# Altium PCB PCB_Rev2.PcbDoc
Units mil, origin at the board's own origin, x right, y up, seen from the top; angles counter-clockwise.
Board outline 1472.44 x 1252.14 mil, 4 copper layers (Top Layer, Layer 1 (GND), Layer 2 (PWR), Bottom Layer), stack 61.2 mil thick; 59 components, 40 nets, 212 pads, 64 vias.
Unrouted connection lines stored in the file: 48.
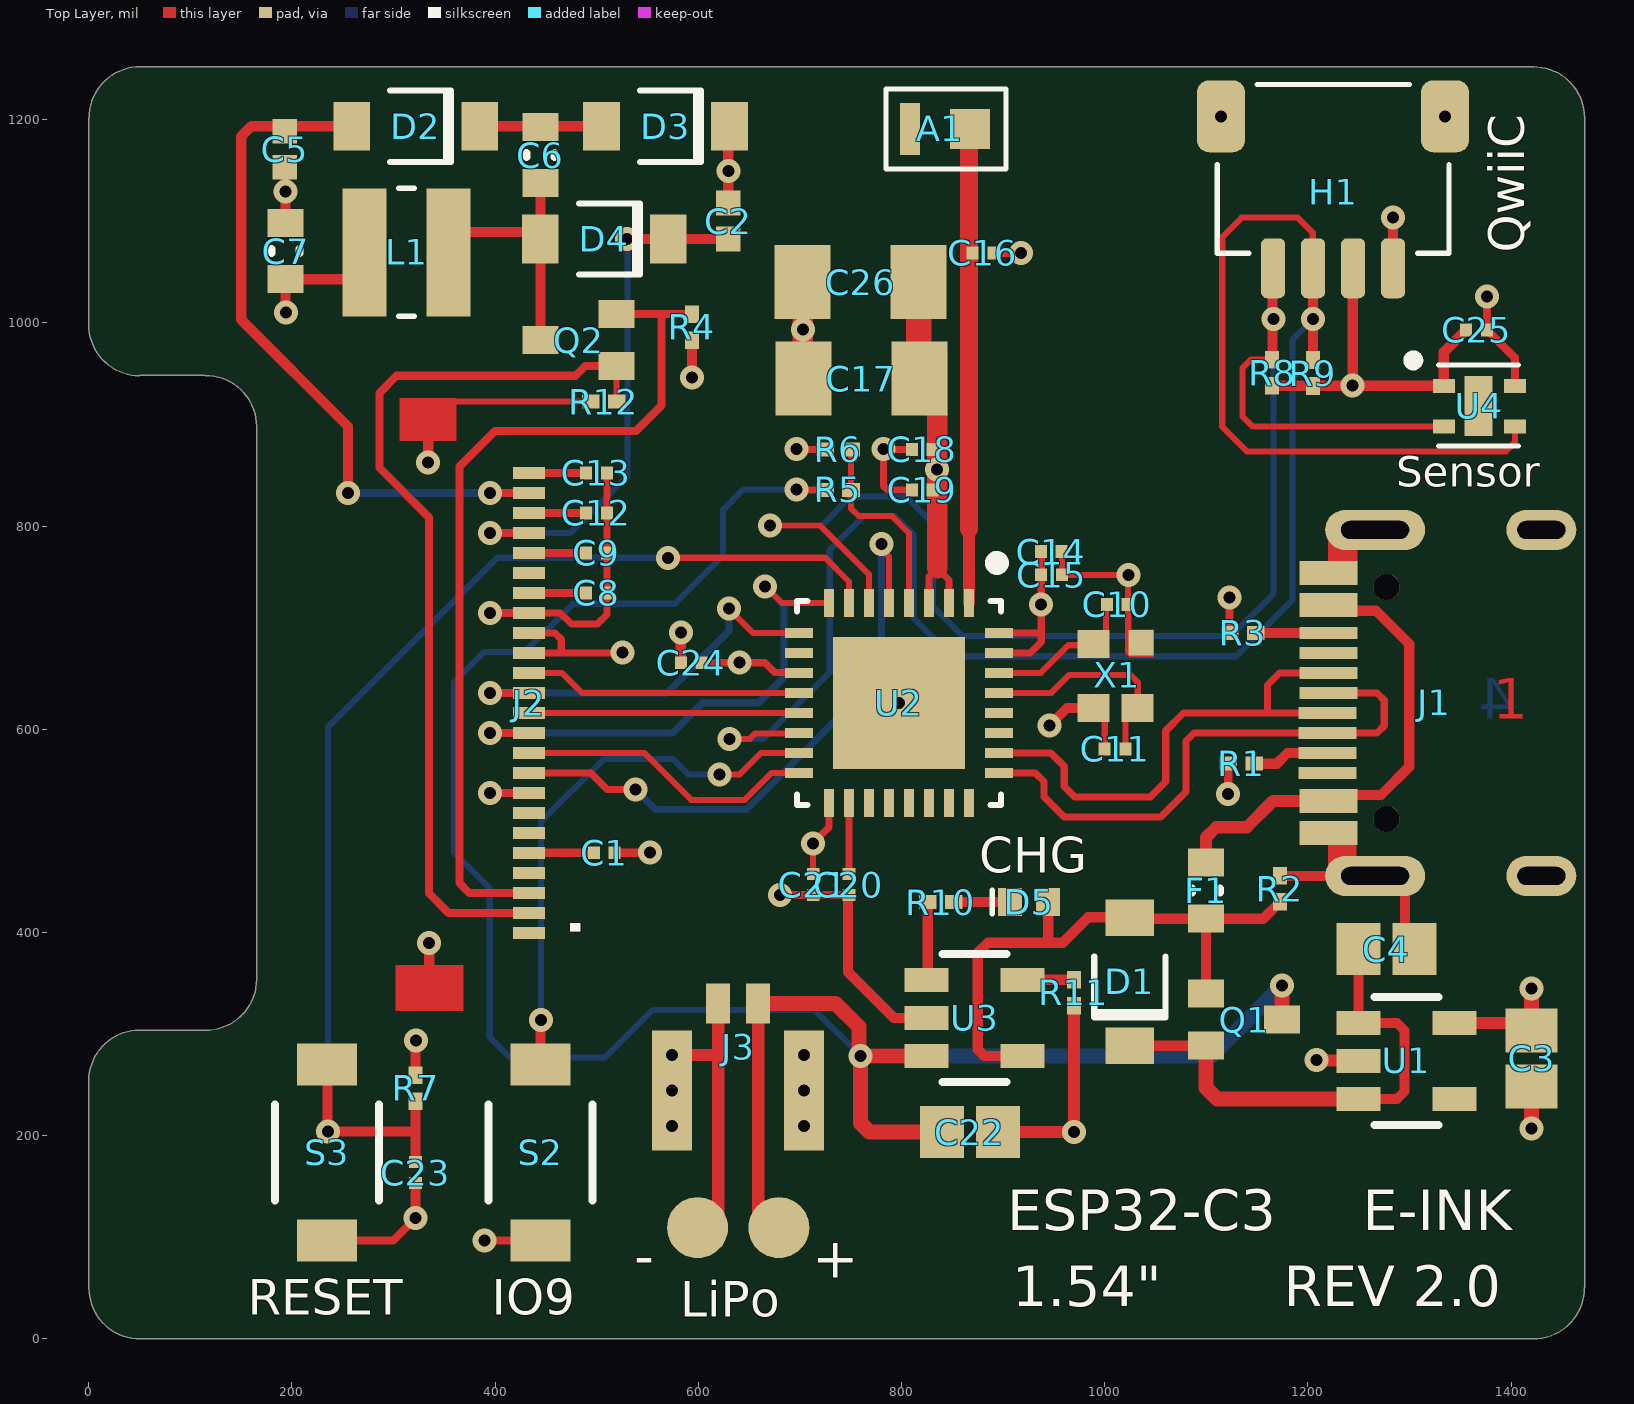
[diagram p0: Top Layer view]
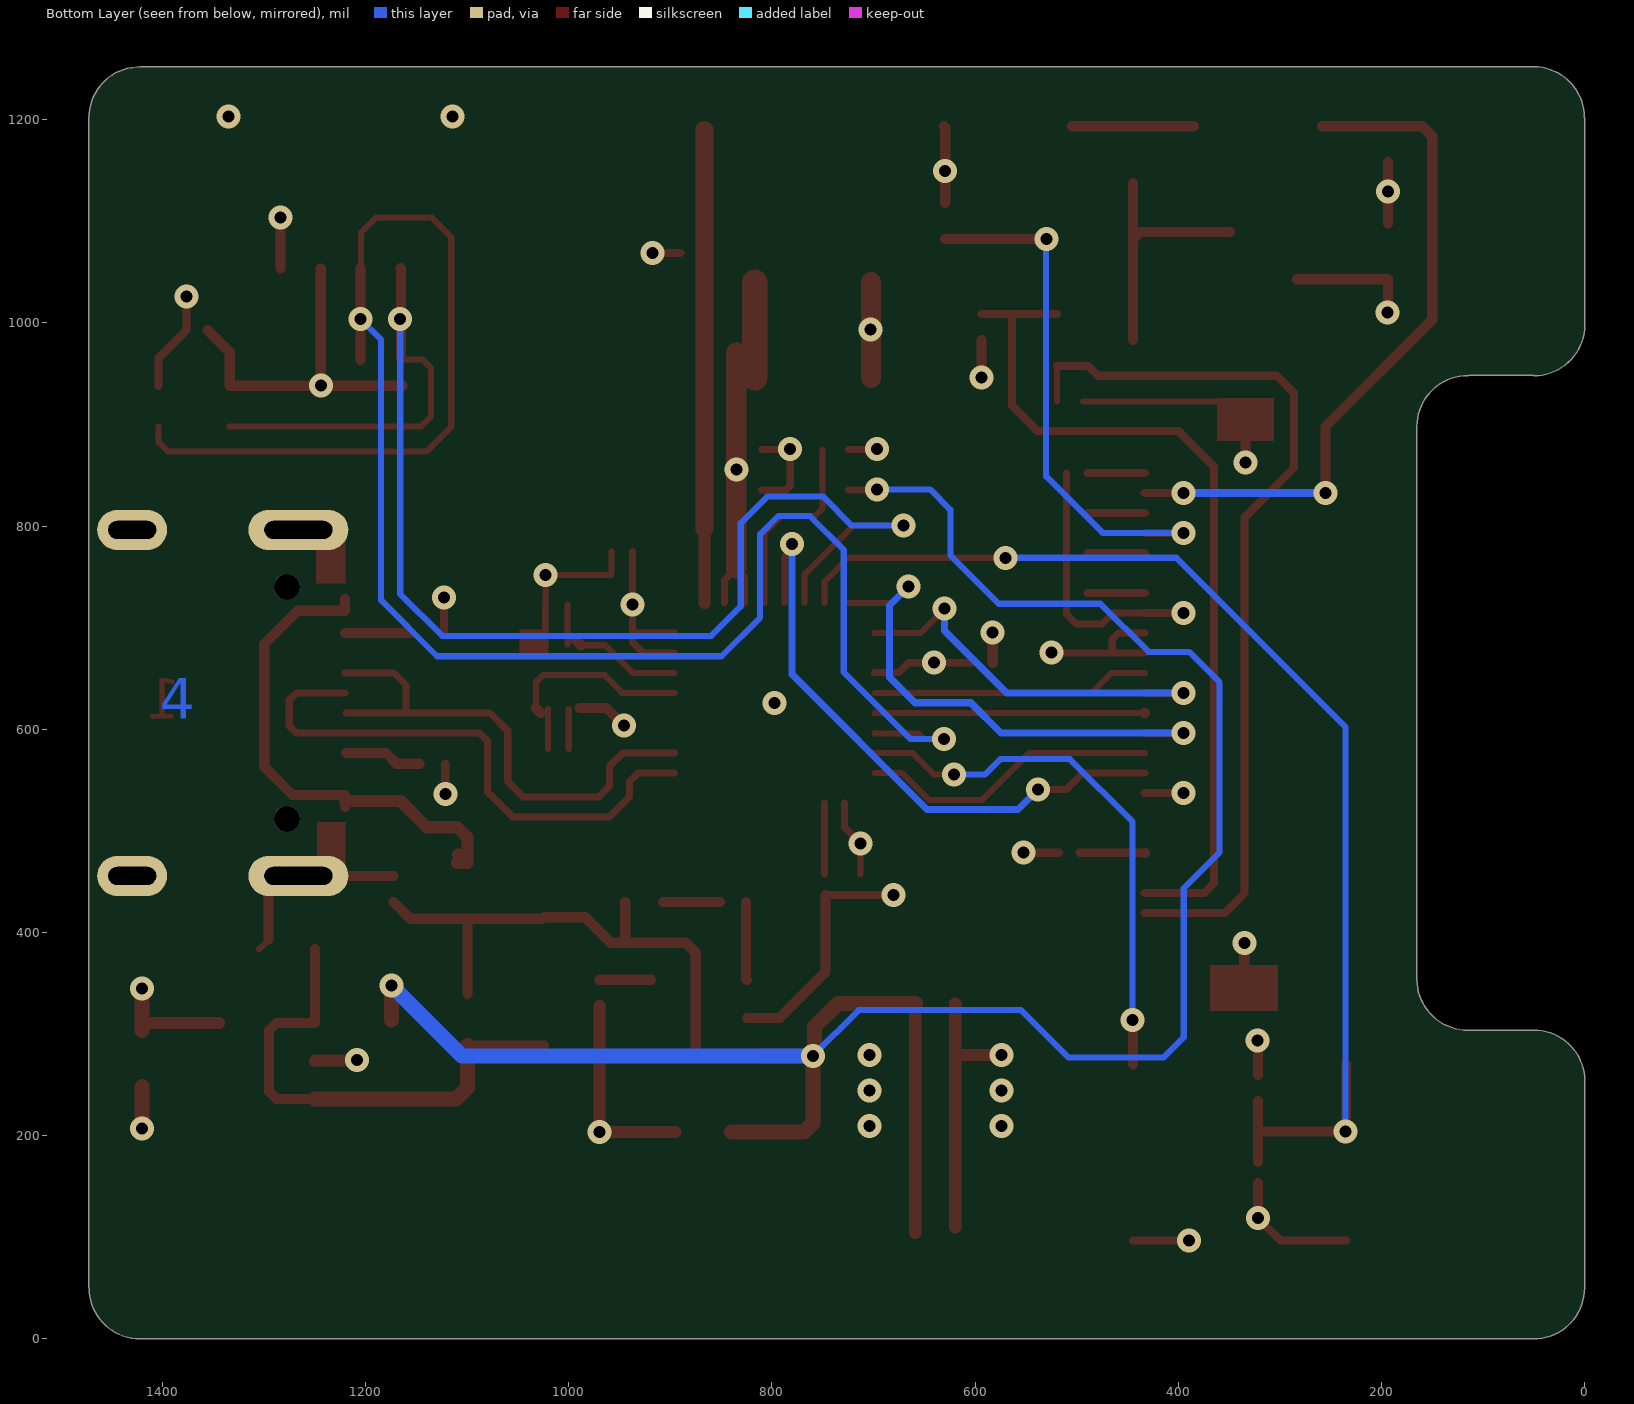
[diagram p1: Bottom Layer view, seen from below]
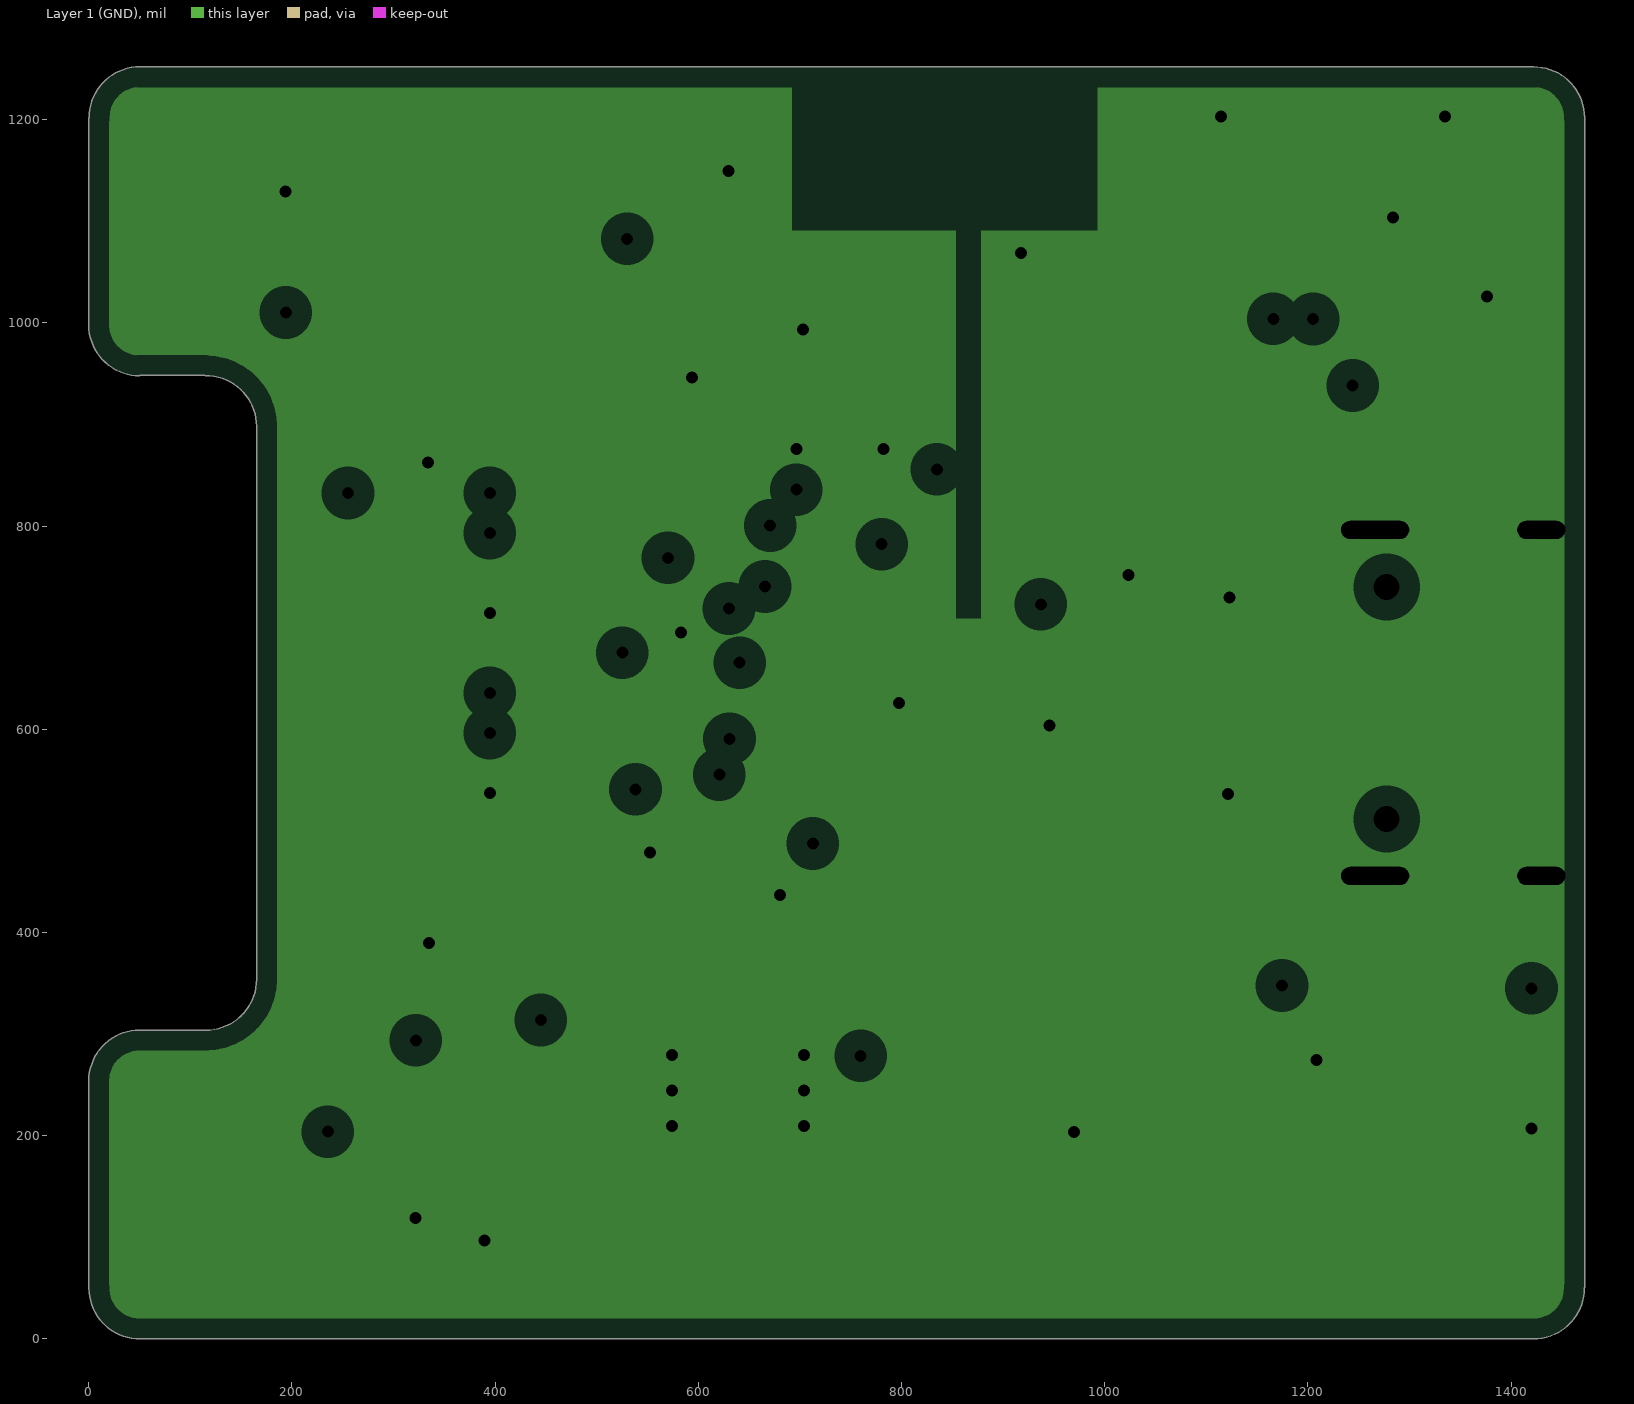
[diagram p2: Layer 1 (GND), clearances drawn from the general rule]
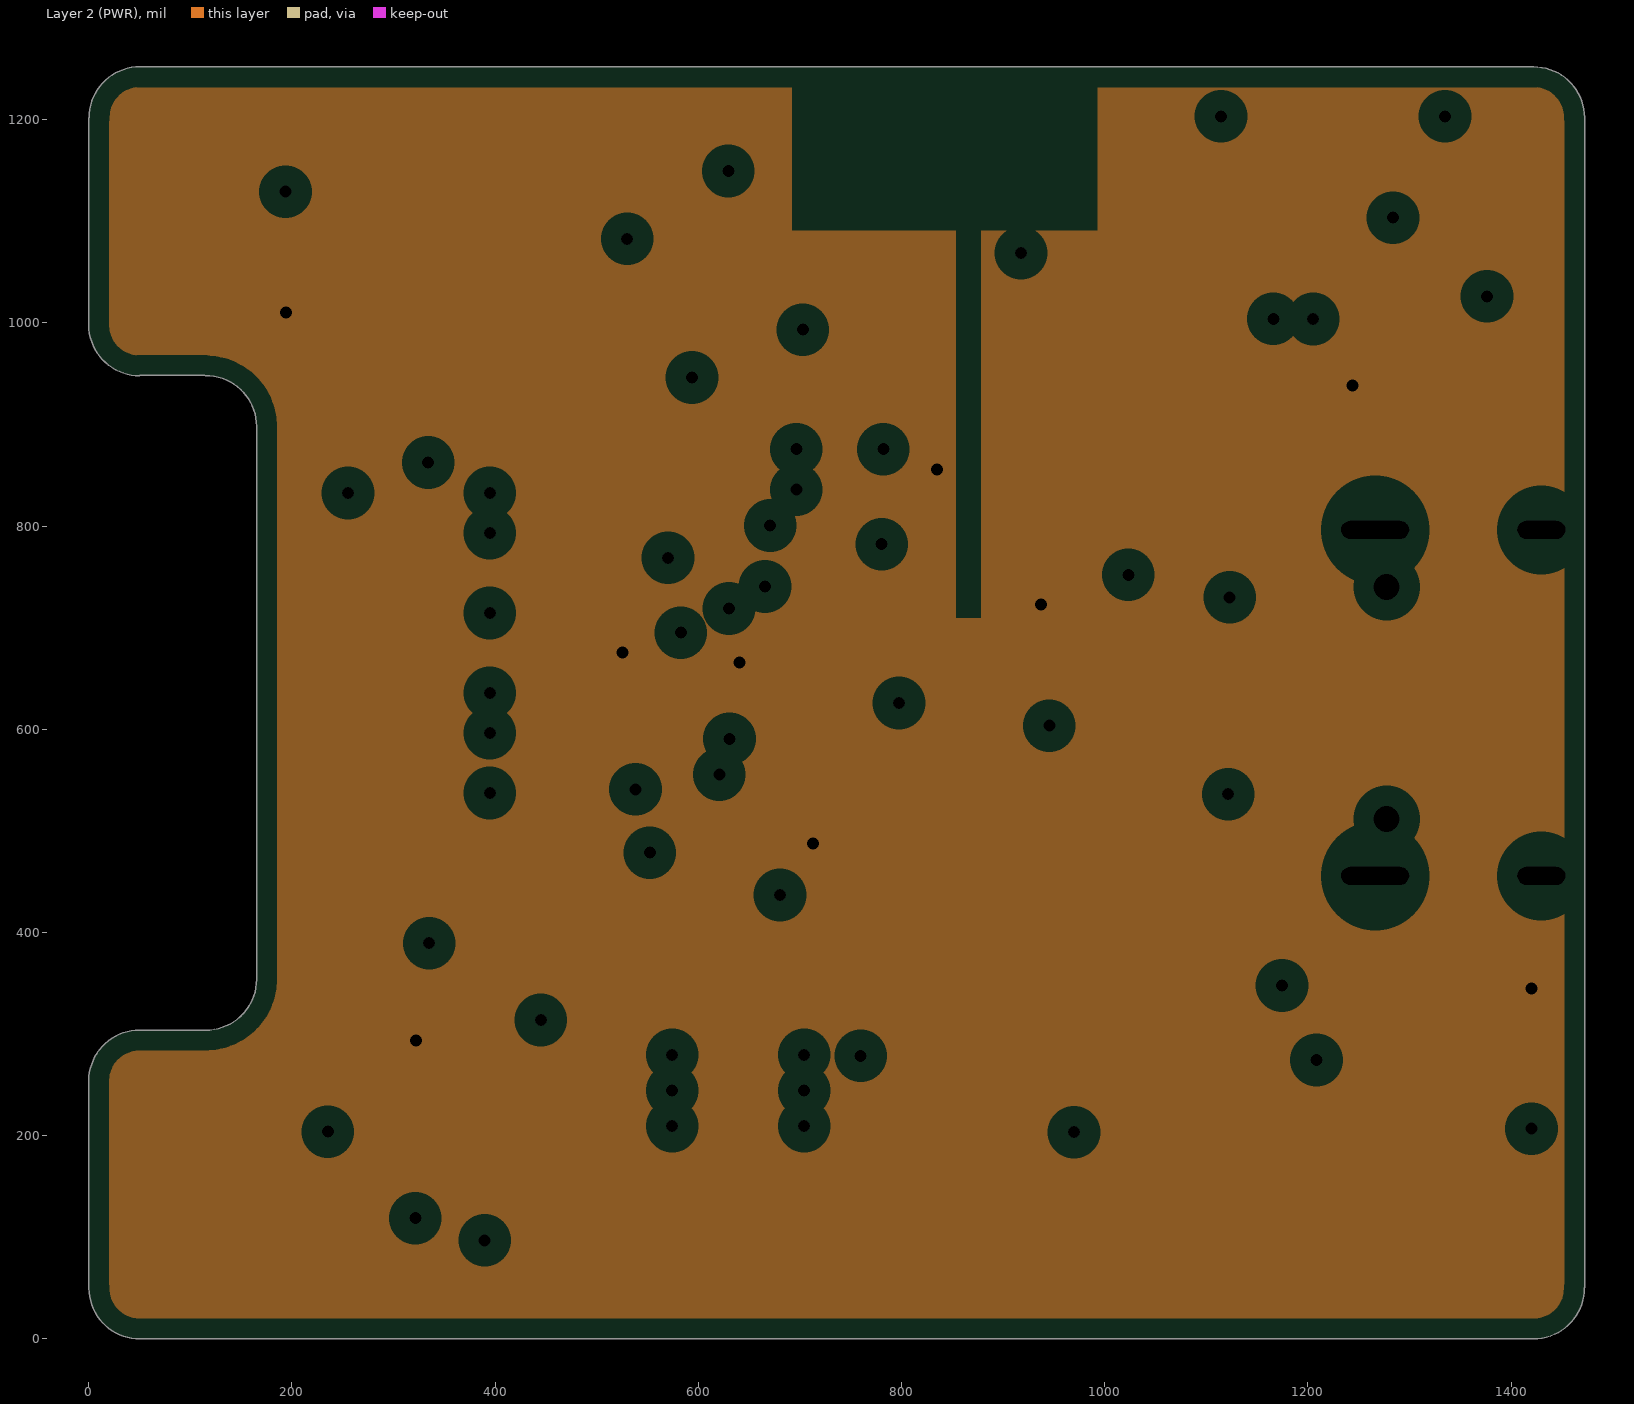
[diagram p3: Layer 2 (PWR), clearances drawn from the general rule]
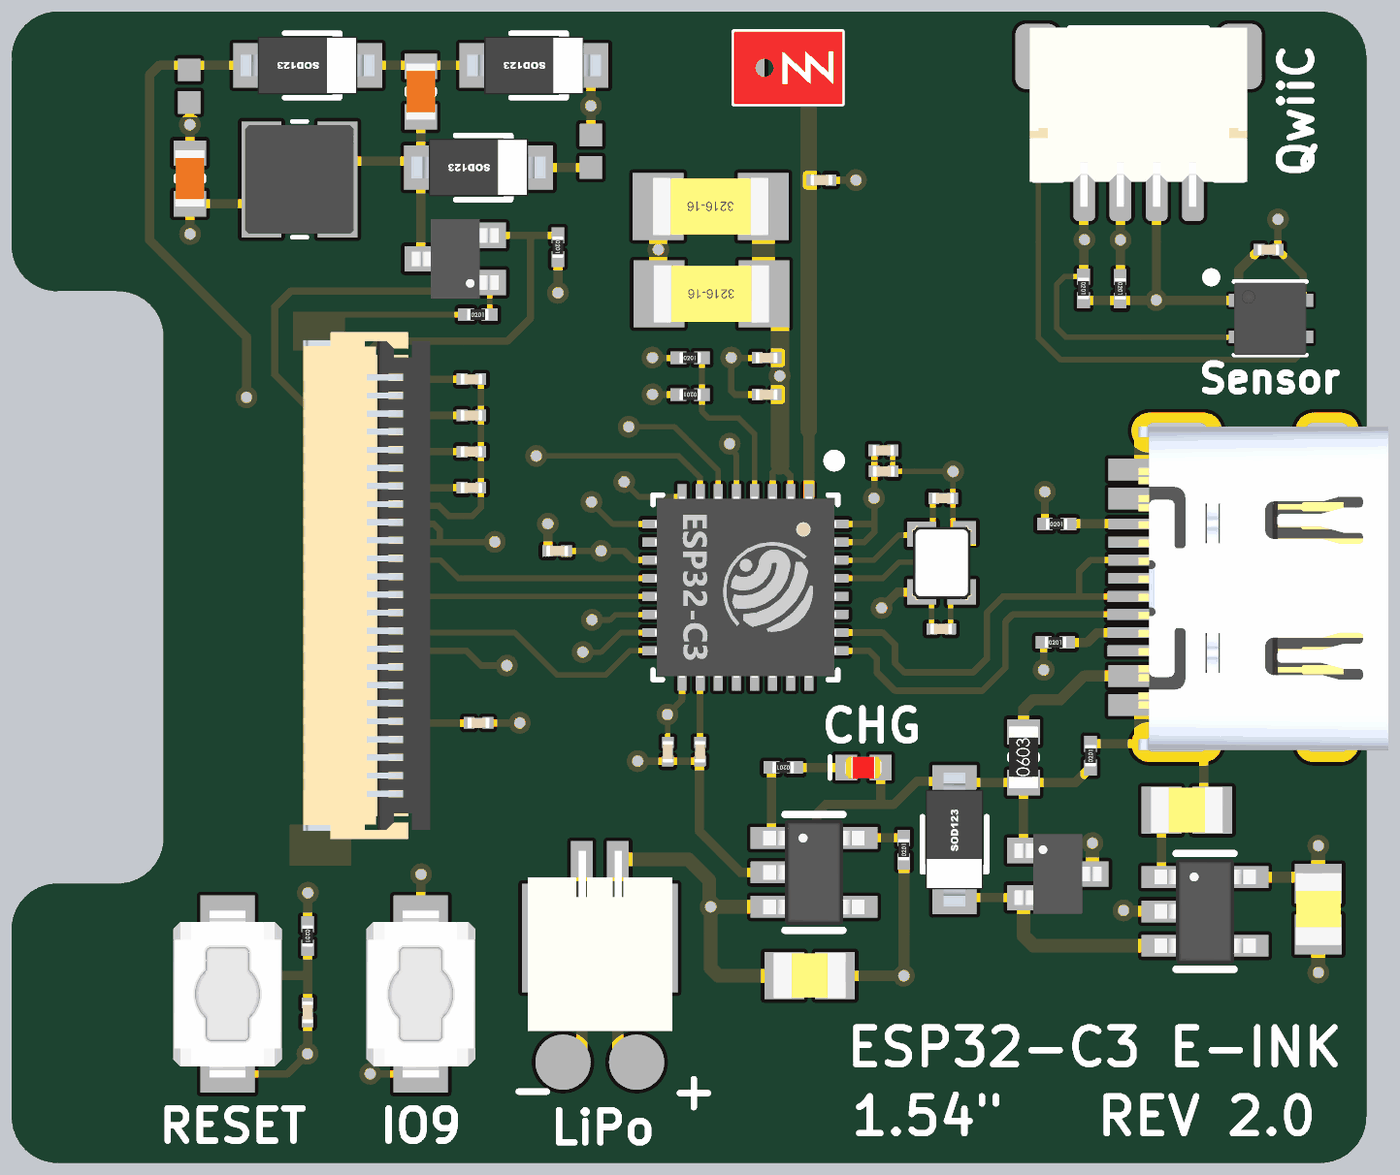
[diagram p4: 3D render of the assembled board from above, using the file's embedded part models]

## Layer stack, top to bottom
Top Solder: solder mask 0.4, Solder Resist, Dk 3.5
Top Layer: signal copper 1.4
Dielectric 2: prepreg 2.8, PP-006, Dk 4.1
Layer 1 (GND): plane copper 1.2, net GND
Dielectric 1: dielectric 50.4, FR-4, Dk 4.8
Layer 2 (PWR): plane copper 1.2, net +3.3V
Dielectric 3: prepreg 2.8, PP-006, Dk 4.1
Bottom Layer: signal copper 1.4
Bottom Solder: solder mask 0.4, Solder Resist, Dk 3.5

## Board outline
0,50 0,253.98 cw(c50,253.9) 50.11,303.9 115.11,303.9 ccw(c115.22,353.9) 165.22,353.82 165.22,898.14 ccw(c115.22,898.06) 115.11,948.06 113.94,948.28 50.11,948.28 50.11,948.06 cw(c50,998.06) 0,997.98 0,1202.03 0.29,1202.03 cw(c50.29,1202.14) 50.22,1252.14 50.22,1251.97 1422.11,1251.97 1422.11,1252.06 cw(c1422.22,1202.06) 1472.22,1202.14 1472.44,1202.14 1472.44,50.25 1472.14,50.25 cw(c1422.14,50.14) 1422.22,0.14 1422.22,0 50.32,0 50.32,0.08 cw(c50.22,50.08)

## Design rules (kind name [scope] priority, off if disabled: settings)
Clearance Clearance_CAP [All vs HasFootprint('CAPC0603X56N')] p1: gap=8.5 ignorepadtopadclearanceinfootprint=FALSE
Clearance Clearance_RES [All vs (HasFootprint('RESC0603X40L (0201 footprint)'))] p2: gap=8.2 ignorepadtopadclearanceinfootprint=FALSE
Clearance Clearance_U4 [All vs InComponent('U4')] p3: gap=5 ignorepadtopadclearanceinfootprint=FALSE
Clearance Clearance_J1 [All vs InComponent('J1')] p4: gap=5 ignorepadtopadclearanceinfootprint=FALSE
Clearance Clearance_J2 [All vs InComponent('J2')] p5: gap=5 ignorepadtopadclearanceinfootprint=FALSE
Clearance Clearance_U2 [All vs InComponent('U2')] p6: gap=5 ignorepadtopadclearanceinfootprint=FALSE
Clearance [All] p7: gap=10 ignorepadtopadclearanceinfootprint=FALSE except(0: Arc-Hole Track-Hole SMDPad-Hole THPad-Hole Via-Hole Fill-Hole Poly-Hole Region-Hole Text-Hole)
MinimumSolderMaskSliver [All] p1: minsoldermaskwidth=0.25
PlaneClearance [All] p1: clearance=20
PlaneConnect PlaneConnect_Via [(IsVia)] p1: planeconnectstyle=Direct reliefexpansion=20 reliefentries=4 reliefconductorwidth=10 reliefairgap=10
PlaneConnect [All] p2: planeconnectstyle=Relief reliefexpansion=20 reliefentries=4 reliefconductorwidth=10 reliefairgap=10
PolygonConnect [All] p1: connectstyle=Relief reliefconductorwidth=10 reliefentries=4 polygonreliefangle="90 Angle" airgapwidth=10
RoutingVias [All] p1: holewidth=28 width=50 viastyle="Through Hole" minholewidth=28 minwidth=50 maxholewidth=28 maxwidth=50
SilkToSilkClearance [All] p1: silktosilkclearance=2
SilkToSolderMaskClearance [IsPad] p1: minsilkscreentomaskgap=2 clearancetoexposedcopper=TRUE
SolderMaskExpansion [All] p1: expansion=4 istentingtop=FALSE
Width [All] p1: maxlimit=30 minlimit=6 preferedwidth=6
25 further rules are at their usual default settings.

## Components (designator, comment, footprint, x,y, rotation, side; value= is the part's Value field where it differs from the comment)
A1 "NN02-101" NN02-101 837.91,1190.98 r180 top value="Chip Antenna"
C1 "1uF" CAPC0603X56N 507.4,478.58 r180 top
C2 "1uF" CAPC1005X56N 629.49,1100.28 r90 top
C3 "10uF" CAPC2012X140N 1420.08,276.02 r270 top
C4 "10uF" CAPC2012X140N 1277.24,383.58 r0 top
C5 "1uF" CAPC1005X56N 193,1171 r90 top
C6 "4.7uF" CAPC1608X09L 444.49,1165.12 r270 top
C7 "4.7uF" CAPC1608X09L 193.69,1070.59 r90 top
C8 "1uF" CAPC0603X56N 499.69,734.25 r180 top
C9 "1uF" CAPC0603X56N 499.69,773.62 r180 top
C10 "10pF" CAPC0603X56N 1012.37,722.98 r180 top
C11 "10pF" CAPC0603X56N 1010.2,580.71 r0 top
C12 "1uF" CAPC0603X56N 499.69,812.99 r180 top
C13 "1uF" CAPC0603X56N 499.69,852.36 r180 top
C14 "1uF" CAPC0603X56N 947.37,774.98 r0 top
C15 "0.1uF" CAPC0603X56N 947.68,752.14 r0 top
C16 "1pF" CAPC0603X56N 880.08,1068.88 r0 top
C17 "100uF" CAPC3216X160N 760.52,945.17 r180 top
C18 "1uF" CAPC0603X56N 820.45,875.57 r0 top
C19 "0.1uF" CAPC0603X56N 820.45,835.57 r180 top
C20 "1uF" CAPC0603X56N 748.15,447.2 r270 top
C21 "0.1uF" CAPC0603X56N 713.15,447.2 r270 top
C22 "10uF" CAPC2012X140N 867.24,203.58 r0 top
C23 "1uF" CAPC0603X56N 321.73,163.8 r270 top
C24 "0.1uF" CAPC0603X56N 592.93,665.58 r180 top
C25 "0.1uF" CAPC0603X56N 1365.97,993.15 r0 top
C26 "100uF" CAPC3216X160N 759.69,1040.17 r180 top
D1 "MBR0520" SOD123 1024.69,351.58 r90 top
D2 "MBR0520-TP" SOD123 321.69,1193.58 r180 top value=MBR0520
D3 "MBR0520-TP" SOD123 567.69,1193.58 r180 top value=MBR0520
D4 "MBR0520-TP" SOD123 507.49,1082.56 r180 top value=MBR0520
D5 "Red Led" LED1005X40N-Red 925.67,430 r0 top
F1 "PTC" "RESC1608X06L (0603 FOOTPRINT)" 1099.69,441.14 r90 top
H1 "QWiiC" SM04B-SRSS-TB 1224.69,1128.58 r180 top locked
J1 "USB-C" TYPE-C-31-M-12 1421.81,796.26 r90 top locked
J2 "24POS Flex Connector" 687124182122 433.07,625.98 r90 top
J3 "CON2" JST_Micro_2PIN 639.21,330.2 r0 top
L1 "68uH" "INDUCTOR, 3mmX3mm" 312.87,1069.57 r180 top
Q1 "LP1480WT1G" SC-70 1137.09,314.17 r0 top
Q2 "AO7400" SC-70 482.09,983.15 r180 top
R1 "5.1K" "RESC0603X40L (0201 footprint)" 1134.33,566.18 r0 top
R2 "100K" "RESC0603X40L (0201 footprint)" 1172.44,442.91 r90 top
R3 "5.1K" "RESC0603X40L (0201 footprint)" 1135.67,694.88 r0 top
R4 "2.2R" "RESC0603X40L (0201 footprint)" 593.69,995.94 r270 top
R5 "100K" "RESC0603X40L (0201 footprint)" 737.39,835.58 r180 top
R6 "100K" "RESC0603X40L (0201 footprint)" 737.39,875.58 r0 top
R7 "10K" "RESC0603X40L (0201 footprint)" 321.73,246.83 r270 top
R8 "10K" "RESC0603X40L (0201 footprint)" 1164.84,951.08 r270 top
R9 "10K" "RESC0603X40L (0201 footprint)" 1204.84,950.67 r270 top
R10 "4.7K" "RESC0603X40L (0201 footprint)" 838.5,430 r180 top
R11 "4K" "RESC0603X40L (0201 footprint)" 969.59,340.69 r90 top
R12 "10K" "RESC0603X40L (0201 footprint)" 506.69,922.56 r0 top
S2 "=Value" TS-1088R-02526 444.69,183.58 r270 top
S3 "=Value" TS-1088R-02526 234.69,183.58 r270 top
U1 "HT7833" SOT95P280X144-5N 1296.93,273.58 r0 top
U2 "ESP32-C3" "VFQFN-32 -ESP32-C3" 797.44,625.98 r270 top locked
U3 "MCP73831T-2ACI/OT" SOT95P280X144-5N 871.93,315.98 r0 top value=MCP73831T-2ACI
U4 "SHTC3" "DFN-4 (2.0mm X 2.0mm)" 1368.69,918.15 r0 top value=Temp/Humid
X1 "40 Mhz" OSC20X16 1012.41,653.16 r270 top

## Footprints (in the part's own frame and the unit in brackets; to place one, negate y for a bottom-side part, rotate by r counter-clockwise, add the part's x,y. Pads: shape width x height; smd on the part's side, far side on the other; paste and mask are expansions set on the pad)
687124182122 [mm] "CONN FFC TOP/BOT 24POS 0.50MM R/A"
  rect 0.3x0.8 smd: 1(-5.75,0) 2(-5.25,0) 3(-4.75,0) 4(-4.25,0) 5(-3.75,0) 6(-3.25,0) 7(-2.75,0) 8(-2.25,0) 9(-1.75,0) 10(-1.25,0) 11(-0.75,0) 12(-0.25,0) 13(0.25,0) 14(0.75,0) 15(1.25,0) 16(1.75,0) 17(2.25,0) 18(2.75,0) 19(3.25,0) 20(3.75,0) 21(4.25,0) 22(4.75,0) 23(5.25,0) 24(5.75,0)
  Top Layer region: -7.696,1.627 -6.55,1.627 -6.55,3.329 -7.696,3.329
  Top Layer region: 6.55,1.805 7.62,1.805 7.62,3.228 6.55,3.228
  body extent -6.95,-0.55 7.05,2.95, height 0.96
CAPC0603X56N [mm] "Chip Capacitor, 2-Leads, Body 0.61x0.3mm, IPC Medium Density (0201 ceramic)"
  rect 0.3x0.32 smd: 1(-0.26,0) 2(0.26,0)
  body extent -0.3,-0.15 0.3,0.15, height 0.3
CAPC1005X56N [mm] "Chip Capacitor, 2-Leads, Body 1.0x0.5mm, IPC Medium Density (0402 ceramic)"
  rect 0.62x0.62 smd: 1(-0.45,0) 2(0.45,0)
  body extent -0.55,-0.3 0.55,0.3, height 0.6
CAPC1608X09L [mm] "Chip Capacitor, 2-Leads, Body 1.6x0.8mm, IPC High Density (0603 dense)"
  rect 0.7x0.9 smd: 1(-0.7,0) 2(0.7,0)
  silkscreen extent -0.05,-0.35 0.05,0.35, body extent -0.89,-0.48 0.88,0.48, height 1.03
CAPC2012X140N [mm] "Chip Capacitor, 2-Leads, Body 2.0x1.3mm, IPC Medium Density (0805 ceramic)"
  rect 1.1x1.3 smd: 1(-0.7,0) 2(0.7,0)
  body extent -1,-0.62 1,0.63, height 1.24
CAPC3216X160N [mm] "Chip Capacitor, 2-Leads, Body 3.2x1.6mm, IPC Medium Density(C1206)"
  rect 1.4x1.85 smd: 1(-1.45,0) 2(1.45,0)
  body extent -1.6,-0.8 1.6,0.8, height 1.89
"DFN-4 (2.0mm X 2.0mm)" [mm] "DFN-4 (2.0mm X 2.0mm)"
  rect 0.55x0.35 smd mask+0.076: 1(-0.889,0.508) 2(-0.889,-0.508) 3(0.889,-0.508) 4(0.889,0.508)
  rect 0.7x1.5 smd paste-0.1 mask+0.076: 7(-0.025,0)
  silkscreen extent -1.78,-1 0.97,1.27, body extent -1.02,-1 0.98,1, height 0.75
"INDUCTOR, 3mmX3mm" [mm] "Inductor, 2-Leads, (3mmX3mm)"
  rect 1.1x3.2 smd: 1(-1.05,0) 2(1.05,0)
  silkscreen extent -0.2,-1.6 0.2,1.6, body extent -1.5,-1.5 1.5,1.5, height 1.5
JST_Micro_2PIN [mm]
  rect 0.6x1 smd: 1(0.5,0) 2(-0.5,0)
  rect 1x3 smd: ""(-1.65,-2.175) ""(1.65,-2.175)
  body extent -1.99,-4.74 2,0.24, height 2.9
LED1005X40N-Red [mm] "Chip LED 2-Leads, Body 1.0x0.5mm, (0402)"
  rect 0.6x0.7 smd: 1(-0.475,0) 2(0.475,0)
  silkscreen extent -0.92,-0.3 -0.92,0.3, body extent -0.5,-0.3 0.5,0.3, height 0.2
NN02-101 [mm] "COMPACT REACH XTEND - 101"
  rect 1x1 smd: 1(-0.75,0)
  rect 0.5x1.3 smd: 2(0.75,0)
  silkscreen extent -1.65,-1 1.35,1, body extent -1.65,-1 1.35,1, height 0.8
OSC20X16 [mm] "Crystal 2.0mm x 1.60mm 0.5mm height"
  rect 0.7x0.8 smd: 1(-0.783,-0.591) 2(0.817,-0.591) 3(0.817,0.509)
  rect 0.635x0.635 smd: 4(-0.817,0.591)
  Top Layer region: -1.138,0.196 -0.554,0.196 -0.453,0.298 -0.453,0.907 -1.138,0.907
  body extent -1.01,-0.87 1.04,0.78, height 0.4
"RESC0603X40L (0201 footprint)" [mm] "Chip Resistor, 2-Leads, Body 0.6x0.3mm, IPC Medium Density (0201)"
  rect 0.44x0.35 smd: 1(-0.325,0) 2(0.325,0)
  body extent -0.3,-0.15 0.3,0.15, height 0.21
"RESC1608X06L (0603 FOOTPRINT)" [mm] "Chip Resistor, 2-Leads, Body 1.6x0.8mm, IPC High Density (0603 dense)"
  rect 0.7x0.9 smd: 1(-0.7,0) 2(0.7,0)
  silkscreen extent -0.05,-0.35 0.05,0.35, body extent -0.85,-0.4 0.85,0.4, height 0.56
SC-70 [mm] "SOT23, 3-Leads, Body 2x1.25mm, Pitch 0.65mm"
  rect 0.9x0.7 smd: 1(-0.95,0.65) 2(-0.95,-0.65) 3(0.95,0)
  body extent -1.2,-1.1 1.2,1.1, height 1
SM04B-SRSS-TB [mm] "CONN HEADER 4POS .100 R/A QWIIC"
  rrect50% 0.6x1.5 smd: 1(1.5,1.9) 2(0.5,1.9) 3(-0.5,1.9) 4(-1.5,1.9)
  rrect50% 1.2x1.8 smd: 5(-2.8,-1.9) 5(2.8,-1.9)
  silkscreen extent -2.9,-2.69 2.9,1.52, body extent -3,-2.69 3,2.26, height 3.25
SOD123 [mil] "Molded Diode, 2-Leads, Body 2.85x1.8mm, IPC Medium Density (SOD123)"
  rect 36x48 smd: 1(-63,0) 2(63,0)
  silkscreen extent -35,-35 25,35, body extent -73,-31 73,31, height 50
SOT95P280X144-5N [mm] "SOT23, 5-Leads, Body 3.1x3.0mm (max), Pitch 0.95mm, IPC Medium Density (RFMD SOT23-5)"
  rect 1.1x0.6 smd: 1(-1.2,0.95) 2(-1.2,0) 3(-1.2,-0.95) 4(1.2,-0.95) 5(1.2,0.95)
  silkscreen extent -0.8,-1.6 0.8,1.6, body extent -1.4,-1.45 1.4,1.45, height 1.45
TS-1088R-02526 [mm] "SWITCH TACTILE SPST-NO 0.05A 12V"
  rect 1.05x1.5 smd: 1(-2.2,0) 2(2.2,0)
  silkscreen extent -1.2,-1.3 1.2,1.3, body extent -2.3,-1.5 2.3,1.5, height 2
TYPE-C-31-M-12 [mm] "USB-C Connector"
  oval 1x1.75 hole 0.45 slot 1.2 at 90 deg: 1(-8.65,-0.2) 1(0,-0.2)
  oval 1x2.5 hole 0.45 slot 1.7 at 90 deg: 1(-8.65,3.955) 1(0,3.955)
  rect 0.3x1.45 smd: A1(-7.726,5.119) A4(-6.926,5.117) A5(-5.575,5.142) A6(-4.575,5.142) A7(-4.075,5.117) A8(-3.075,5.117) A9(-1.727,5.117) A12(-0.924,5.117) B1(-1.224,5.117) B4(-2.021,5.117) B5(-2.575,5.117) B6(-3.575,5.117) B7(-5.075,5.142) B8(-6.075,5.142) B9(-6.626,5.117) B12(-7.426,5.119)
  round 0.65 hole 0.65 unplated: ""(-7.225,3.667) ""(-1.425,3.667)
  body extent -8.82,-1.89 0.12,5.01, height 3.31
"VFQFN-32 -ESP32-C3" [mm] "Quad Flat Pack 32 Pin 5x5x0.85mm"
  rect 0.7x0.25 smd: 1(-2.5,1.75) 2(-2.5,1.25) 3(-2.5,0.75) 4(-2.5,0.25) 5(-2.5,-0.25) 6(-2.5,-0.75) 7(-2.5,-1.25) 8(-2.5,-1.75) 17(2.5,-1.75) 18(2.5,-1.25) 19(2.5,-0.75) 20(2.5,-0.25) 21(2.5,0.25) 22(2.5,0.75) 23(2.5,1.25) 24(2.5,1.75)
  rect 0.25x0.7 smd: 9(-1.75,-2.5) 10(-1.25,-2.5) 11(-0.75,-2.5) 12(-0.25,-2.5) 13(0.25,-2.5) 14(0.75,-2.5) 15(1.25,-2.5) 16(1.75,-2.5) 25(1.75,2.5) 26(1.25,2.5) 27(0.75,2.5) 28(0.25,2.5) 29(-0.25,2.5) 30(-0.75,2.5) 31(-1.25,2.5) 32(-1.75,2.5)
  rect 3.3x3.3 smd paste-5 mask+0.102: 33(0,0)
  silkscreen extent -3.65,-2.55 2.55,2.6, body extent -2.5,-2.5 2.5,2.5, height 1.12

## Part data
A1: "Antenna Chip 2.4Gig", Manufacturer=Ignion
C1 C8 C9 C12 C13 C14 C18 C20 C23: library part CAP_0201, "CAP 1uF 0201"
C2 C5: library part CAP_0402, "CAP 1uF 0402"
C3 C4 C22: library part CAP_0805, "CAP 10uF 0805"
C6 C7: library part CAP_0603, "CAP 4.7uF 50V 0603"
C10 C11: library part CAP_0201, "CAP 10pF 0201"
C15 C19 C21 C24 C25: library part CAP_0201, "CAP 0.1uF 0201"
C16: library part CAP_0201, "CAP 1pF 0201"
C17 C26: library part CAP_1206, "CAP 100uF 1206"
D1: library part MBR0520-TP, "DIODE SCHOTTKY 20V 500MA SOD-123", Manufacturer=Micro
D2 D3 D4: "DIODE SCHOTTKY 20V 500MA SOD-123", Manufacturer=Micro
D5: library part LED_0402_SMALL_Red, "LED Red 0402", Manufacturer=Lite-On
F1: library part PTC_FUSE_0603, "PTC FUSE ?mA hold, ?A trip 0603"
H1: library part SM04B-SRSS-TB, "CONN HEADER 4POS .100 R/A QWIIC", Manufacturer=JST
J1: "CONN RECPT USB-C", Manufacturer=KHE
J2: library part 687124182122, "CONN FFC TOP/BOT 24POS 0.50MM R/A", Manufacturer=Wurth
J3: library part JST_Micro_CONN_2PIN, "JST MIcro CONN 2POS"
L1: "INDUCTOR 68uH 20% 4mmx4mm", Manufacturer=SXN
Q1: "MOSFET P-CH 20V 1.4A SC-70", Manufacturer=LRC
Q2: "MOSFET N-CH 20V 4A SC70-3", Manufacturer="VBSemi Elec"
R1 R3: library part RES_0201, "RES 0201 5.1K"
R2 R5 R6: library part RES_0201, "RES 100K 0201"
R4: library part RES_0201, "RES 2.2R 0201"
R7 R8 R9 R12: library part RES_0201, "RES 10K 0201"
R10: library part RES_0201, "RES 4.7K 0201"
R11: library part RES_0201, "RES 4K 0201"
S2 S3: library part TS-1088R-02526, "Tactile Micro Switch", Manufacturer=XUNPU
U1: "IC LDO 3.3V 0.5A SOT23-5", Manufacturer=Holtek
U2: "WIFI/Bluetooth, VFQFN-32", Manufacturer=Espressif
U3: "Charger IC Lithium-Ion/Polymer SOT23-5", Manufacturer=Microchip
U4: "Humidity/Temperature Sensor", Manufacturer=Sensirion
X1: library part 40Mhz, "CRYSTAL 40MHZ 10PF SMD", Manufacturer=ECS

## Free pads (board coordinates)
  round 60 smd: 2(599.21,109.57) 2(679.21,109.57)

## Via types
v1: diameter 23.62, hole 11.81, Top Layer to Bottom Layer, tented both sides, 64 vias

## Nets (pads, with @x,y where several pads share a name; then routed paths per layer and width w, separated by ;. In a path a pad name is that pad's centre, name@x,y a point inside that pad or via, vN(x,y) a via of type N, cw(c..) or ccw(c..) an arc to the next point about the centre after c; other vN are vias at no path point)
+3.3V: C3.1 C7.1 C14.1 C15.1 C17.1 C18.2 C19.1 C21.1 C24.1 C25.1 C26.1 H1.3 J2.15 J2.16 L1.2 R7.1 R8.2 R9.2 U1.5 U2.2 U2.3 U2.11 U2.17 U2.31 U2.32 U4.1 | length 1504.2
  Top Layer w6: v1(712.7,487.7) 712.92,487.47 712.92,457.67 C21.1 ; C17.1@813.36,946.41 C17.1@814.19,945.58 ; v1(1243.94,938.41) v1@1244.16,938.62 ; H1.3@1244.16,1053.57 H1.3
  Top Layer w7: J2.15 465.08,675.2 ; J2.16 458.78,694.88 465.08,688.58 465.08,675.2 ; v1@524.84,675.2 465.08,675.2 ; C24.1 v1(640.65,665.58) 665.65,665.58 675.48,655.75 698.78,655.75 U2.11@698.94,655.59 ; v1(712.7,487.7) 728.54,503.54 U2.17 ; U2.3 826.97,750.47 835.08,758.58 846.57,747.09 U2.2@846.57,724.49 ; U2.31 926.69,675.2 937.44,685.95 937.44,694.88 ; U2.32 937.44,694.88 ; C14.1@937.44,774.98 C15.1 937.44,723.29 v1(937.13,722.98) 937.44,722.68 937.44,694.88
  Top Layer w10: v1@193.69,1009.98 C7.1 L1.2@283.32,1043.03 ; R7.1 v1@321.73,293.56 ; R8.2@1163.69,938.15 1204.84,938.15 v1@1243.69,938.15 ; v1(1243.94,938.41) v1@1243.69,938.15 ; v1@1244.16,938.62 H1.3@1244.16,1053.57 ; C25.1 1333.69,971.1 U4.1 v1@1243.69,938.15 ; C3.1@1412.68,310.98 C3.1
  Top Layer w12: U1.5 C3.1@1412.68,310.98
  Top Layer w15: C3.1 v1(1420.08,345)
  Top Layer w20: 835.08,758.58 835.08,780.84 835.08,835.58 835.08,855.97 835.08,875.58 C17.1@835.08,970.58
  Top Layer w25: C17.1@816.78,946 C26.1
  other v1: 321.98,293.81 525.1,675.45 834.69,855.97 193.94,1010.23
A0: R5.1 R6.2 U2.4 | length 194
  Top Layer w6: R6.2 750.19,817.58 757.62,810.15 790.36,810.15 807.28,793.23 U2.4
D+: J1.A6 J1.B6 U2.26 | length 509.3
  Top Layer w7: U2.26 946.89,576.77 960.08,563.58 960.08,543.58 970.08,533.58 1045.08,533.58 1060.08,548.58 1060.08,598.58 1077.64,616.14 1160.08,616.14 ; J1.A6 1160.08,616.14 ; J1.B6 1172.01,655.51 1160.08,643.58 1160.08,616.14
D-: J1.A7 J1.B7 U2.25 | length 555.3
  Top Layer w7: U2.25 931.57,557.09 940.08,548.58 940.08,533.58 960.08,513.58 1055.08,513.58 1080.08,538.58 1080.08,588.58 1087.95,596.46 J1.B7 1267.95,596.46 1275.08,603.58 1275.08,628.58 1267.83,635.83 J1.A7
E-INK_BSY: J2.9 U2.5 | length 606
  Top Layer w6: v1(780.33,782.18) 780.33,777.41 787.6,770.14 U2.5
  Top Layer w7: J2.9 494.14,557.09 510.35,540.88 v1(538.1,540.88)
  Bottom Layer w7: v1(538.1,540.88) 557.8,521.18 647.28,521.18 780.33,654.23 v1(780.33,782.18)
E-INK_CS: J2.12 U2.13 | length 265.9
  Top Layer w6: J2.12 U2.13
E-INK_DC: J2.11 U2.8 | length 517.1
  Top Layer w6: v1(665.65,740.58) 681.82,724.41 U2.8
  Top Layer w8: v1(394.84,596.46) J2.11
  Bottom Layer w7: v1(394.84,596.46) 574.54,596.46 604.27,626.18 659.33,626.18 684.33,651.18 684.33,721.9 v1(665.65,740.58)
E-INK_RST: J2.10 U2.16 | length 296.1
  Top Layer w6: J2.10 546.69,576.77 592.88,530.58 645.65,530.58 672.15,557.09 U2.16
EN: C23.1 R7.2 S3.1 U2.7 | length 1223.7
  Top Layer w6: v1(570.1,768.88) 724.78,768.88 748.15,745.51 U2.7@748.15,724.49
  Top Layer w10: S3.1 235.08,269.8 v1@235.08,203.78 ; v1(235.33,204.04) 321.73,204.04 ; C23.1 321.73,204.04 ; R7.2 321.73,204.04
  Bottom Layer w6: v1(235.33,204.04) 235.33,602.18 402.03,768.88 v1(570.1,768.88)
GDR: J2.2 Q2.1 R12.2 | length 898.3
  Top Layer w6: R12.2 Q2.1
  Top Layer w8: J2.2 354.17,419.29 334.84,438.62 334.84,808.62 286,857.46 286,931 303,948 479.1,948 488.66,957.56 Q2.1
GND: C1.1 C2.2 C3.2 C4.2 C5.1 C7.2 C8.1 C9.1 C10.1 C11.1 C12.1 C13.1 C14.2 C15.2 C16.2 C17.2 C18.1 C19.2 C20.2 C21.2 C22.2 C23.2 C24.2 C25.2 C26.2 D3.1 H1.4 H1.5 J1.1 J1.A1 J1.A12 J1.B1 J1.B12 J2.8 J2.17 J3. J3.2 pad.2@599.21,109.57 R1.1 R2.2 R3.1 R4.2 R6.1 R11.1 R12.1 S2.2 S3.2 U1.2 U2.33 U3.2 U4.4 X1.2 X1.4 | length 2647.2
  Top Layer w6: 334.08,891.58 334.49,891.99 334.49,912.56 344.49,922.56 R12.1 ; C17.2@699.19,946.41 C17.2@700.02,945.58 ; C14.2 957.76,774.83 957.76,752.29 C15.2 957.99,752.06 1023.06,752.06 v1(1023.13,751.98) 1022.87,751.72 1022.87,723.25 C10.1 ; C11.1 X1.2@999.97,619.98 ; 1023.13,683.71 C10.1@1023.13,722.98 ; J1.1@1266.1,455.71 1286.6,455.71 J1.1@1295.39,446.92 ; C4.2@1295.39,392.99 C4.2
  Top Layer w7: J2.17 464.09,714.57 475.08,703.58 500.51,703.58 509.92,712.99 C13.1 ; v1@696.17,875.58 R6.1 ; v1(782.04,875.82) 782.04,839.67 786.14,835.57 C19.2 ; v1@782.29,875.57 C18.1
  Top Layer w8: S3.2 299.65,96.97 v1(321.47,118.79) ; v1(389.69,96.97) S2.2 ; v1(394.84,537.4) J2.8 ; v1(394.84,714.57) J2.17 ; C1.1 v1(552.2,478.58) ; v1(680.39,436.97) C20.2 ; C16.2 v1(917.53,1068.88) ; v1(1121.54,536.18) R1.1 ; R3.1 v1(1122.87,729.88) ; v1(1376.2,1026.18) C25.2 1403.69,965.67 U4.4
  Top Layer w10: C7.2 v1(193.69,1129.15) C5.1@193.69,1158.15 ; v1@321.73,119.04 C23.2 ; v1(334.08,862.58) 334.08,891.58 ; 335.08,360.58 v1(335.08,389.58) ; C24.2 v1(582.69,695.15) ; v1(593.69,946.26) R4.2 ; C2.2@629.69,1117.99 629.49,1118.19 629.49,1192.39 D3.1 ; C20.2@747.44,436.97 747.44,360.83 792.28,315.98 U3.2 ; v1(945.39,603.58) 962.8,620.98 X1.2 ; R2.2 J1.1@1266.1,455.71 ; H1.4 v1(1283.74,1103.58) ; C4.2@1295.39,392.99 J1.1@1295.39,446.92
  Top Layer w12: v1(574.25,279.57) 612.5,279.57 ; pad.2@619.53,109.57 J3.2 ; C22.2 v1(969.69,203.58) R11.1@969.69,327.89 ; v1(1208.39,274.58) 1208.89,274.08 1249.19,274.08 U1.2
  Top Layer w15: v1(1420.08,207.05) C3.2
  Top Layer w20: C17.2@702.6,946 C26.2
  other v1: 574.25,209.57 704.17,209.57 574.25,244.57 704.17,244.57 704.17,279.57 797.44,625.98 696.42,875.84 702.86,993.34 629.49,1149.56 1114.45,1203.39 1334.92,1203.39
GPIO2: H1.1 R8.1 U2.6 U4.2 | length 1417.9
  Top Layer w6: v1(670.65,800.58) 719.93,800.58 767.91,752.6 U2.6 ; R8.1@1165.16,963.88 R8.1 1143.84,963.88 1135.69,955.72 1135.69,907.78 1145.32,898.15 U4.2
  Top Layer w10: R8.1@1165.16,963.88 1165.16,1053.31 H1.1
  Bottom Layer w6: v1(670.65,800.58) 721.3,800.58 749.69,828.97 804.69,828.97 830.69,802.97 830.69,720.97 859.69,691.97 1124.69,691.97 1165.89,733.17 v1(1165.89,1004.04)
GPIO8: H1.2 R9.1 U2.14 U4.3 | length 1932.2
  Top Layer w6: v1(630.65,590.58) 650.65,590.58 656.08,596.02 698.58,596.02 U2.14 ; H1.2 1204.67,1054.11 1204.67,1088.79 1189.84,1103.62 1134.84,1103.62 1115.69,1084.46 1115.69,897.78 1139.84,873.62 1394.84,873.62 1403.69,882.46 U4.3
  Top Layer w10: R9.1 1204.84,1053.62 H1.2
  Bottom Layer w6: v1(630.65,590.58) 663.73,590.58 729.33,656.18 729.33,776.61 762.69,809.97 793.69,809.97 811.69,791.97 811.69,709.97 849.69,671.97 1129.69,671.97 1184.69,726.97 1184.69,983.46 v1(1205.1,1003.88)
GPIO9: S2.1 U2.15 | length 533.1
  Top Layer w6: v1(620.65,555.58) 640.65,555.58 661.83,576.77 U2.15
  Top Layer w10: S2.1 v1@444.69,313.62
  Bottom Layer w6: v1(444.94,313.88) 444.94,508.84 506.78,570.68 575.1,570.68 590.2,555.58 v1(620.65,555.58)
LiPO: C22.1 J3.1 pad.2@679.21,109.57 Q1.3 R5.2 U3.3 | length 2288
  Top Layer w7: v1@696.17,835.58 R5.2
  Top Layer w12: pad.2@658.9,104.57 J3.1
  Top Layer w15: J3.1 735.07,330.2 758.04,307.23 758.04,280.23 v1(759.69,278.58) ; U3.3@814.69,278.58 v1(759.69,278.58) ; C22.1 768.47,203.58 759.69,212.37 v1(759.69,278.58) ; Q1.3 v1(1174.49,347.83)
  Bottom Layer w6: v1@693.13,836.24 644.39,836.24 624.33,816.18 624.33,771.18 576.77,723.62 476.77,723.62 429.33,676.18 389.33,676.18 359.33,646.18 359.33,478.94 394.69,443.58 394.69,296.97 414.69,276.97 508.07,276.97 554.69,323.58 714.69,323.58 v1(759.69,278.58)
  Bottom Layer w15: v1(759.69,278.58) 1105.24,278.58 v1(1174.49,347.83)
  other v1: 696.42,835.84
MISO: U2.10
MOSI: J2.14 U2.12 | length 274.1
  Top Layer w6: J2.14 465.72,655.51 485.4,635.83 U2.12
NetA1_1: A1.1 C16.1 U2.1 | length 467
  Top Layer w10: A1.1@866.34,1189.88 A1.1
  Top Layer w12: U2.1 866.34,797.44
  Top Layer w18: 866.34,797.44 A1.1@866.34,1189.88
NetC1_2: C1.2 J2.5 | length 64.1
  Top Layer w8: J2.5@433.19,478.46 C1.2@497.17,478.46
  Top Layer w10: J2.5 J2.5@433.19,478.46
NetC4_1: C4.1 D1.1 Q1.2 U1.1 U1.3 | length 500.5
  Top Layer w10: D1.1 Q1.2 ; U1.3 1287.68,236.18 1295.08,243.58 1295.08,303.58 1287.68,310.98 U1.1 C4.1
  Top Layer w15: Q1.2 1099.69,247.2 1110.71,236.18 U1.3
NetC6_1: C6.1 D2.1 D3.2 | length 120
  Top Layer w10: D2.1 444.69,1193.58 D3.2
NetC6_2: C6.2 D4.2 L1.1 Q2.3 | length 252.6
  Top Layer w10: L1.1@349.19,1089.57 437.48,1089.57 441.79,1085.26 D4.2 ; Q2.3 444.69,1082.56 444.69,1088.15 C6.2@444.69,1137.56
NetC8_2: C8.2 J2.18 | length 56.4
  Top Layer w8: J2.18 C8.2
NetC9_2: C9.2 J2.20 | length 56.4
  Top Layer w8: J2.20 C9.2
NetC10_2: C10.2 U2.30 X1.1 | length 152.7
  Top Layer w6: U2.30 937.01,655.51 964.24,682.75 X1.1@987.9,682.75 ; X1.1@1001.13,683.71 C10.2@1001.13,722.98
  Top Layer w10: X1.1@987.9,682.75 X1.1 X1.1@995.08,689.93
NetC11_2: C11.2 U2.29 X1.3 | length 218.6
  Top Layer w6: U2.29 947.32,635.83 965.08,653.58 1025.08,653.58 1032.44,646.22 X1.3 ; C11.2 X1.3@1020.44,619.98
  Top Layer w10: X1.3@1027.44,615.98 X1.3
NetC12_2: C12.2 J2.22 | length 56.4
  Top Layer w8: J2.22 C12.2
NetC13_2: C13.2 J2.24 | length 56.4
  Top Layer w8: J2.24 C13.2
NetC20_1: C20.1 U2.18 | length 70
  Top Layer w7: C20.1 U2.18@748.15,527.48
NetD5_1: D5.1 R10.1 | length 55.7
  Top Layer w10: R10.1 D5.1
NetF1_2: F1.2 J1.A4 J1.A9 J1.B4 J1.B9 | length 509.5
  Top Layer w10: J1.A4 1220.36,529.48 J1.B9 1271.88,535.38 1299.69,563.19 1299.69,683.98 1266.98,716.68 J1.B4 J1.A9
  Top Layer w12: F1.2@1108.72,476.48 F1.2@1100.94,468.7 ; F1.2@1109.8,468.7 F1.2@1100.94,468.7 ; J1.B9@1220.36,529.48 1165.59,529.48 1139.69,503.58 1109.69,503.58 1099.69,493.58 F1.2 F1.2@1100.94,468.7
NetJ1_A5: J1.A5 R1.2 | length 76.6
  Top Layer w10: R1.2 1169.33,566.18 1179.92,576.77 J1.A5
NetJ1_B5: J1.B5 R3.2 | length 65
  Top Layer w10: R3.2@1155.35,694.88 J1.B5
NetR10_2: R10.2 U3.1 | length 77
  Top Layer w10: U3.1 825.71,354.41 R10.2
NetR11_2: R11.2 U3.5 | length 50.6
  Top Layer w10: U3.5 919.27,353.48 R11.2 R11.2@969.69,353.58
RESE: J2.3 Q2.2 R4.1 | length 870.2
  Top Layer w8: J2.3 374.49,438.98 364.84,448.62 364.84,858.62 399.96,893.74 538.69,893.74 563.69,918.74 563.69,1008.74 ; Q2.2 563.69,1008.74 ; R4.1 563.69,1008.74
SCLK: J2.13 U2.9 | length 399.7
  Top Layer w6: v1@629.89,718.62 653.63,694.88 U2.9
  Top Layer w8: v1(394.84,635.83) J2.13
  Bottom Layer w7: v1(394.84,635.83) 568.98,635.83 630.14,696.99 v1(630.14,718.88)
VBUS: D1.2 D5.2 F1.1 Q1.1 R2.1 U3.4 | length 574.6
  Top Layer w10: U3.4 881.42,278.58 875,285 875,380 885,390 958.7,390 983.7,415 1024.27,415 D1.2 1025.69,413.58 F1.1 ; 944.37,390.63 D5.2 ; Q1.1 F1.1 ; F1.1@1099.69,413.78 F1.1 ; R2.1 1155.91,413.58 F1.1
VGH: C2.1 D4.1 J2.21 | length 535.8
  Top Layer w8: v1(394.84,793.31) J2.21
  Top Layer w10: v1@529.65,1082.56 D4.1 C2.1
  Bottom Layer w6: v1(394.84,793.31) 474.41,793.31 530.1,849 v1@530.1,1088.41
  other v1: 529.9,1082.82
VGL: C5.2 D2.2 J2.23 | length 685.1
  Top Layer w8: v1(394.84,832.68) J2.23
  Top Layer w10: v1(255.22,832.68) 255.22,898.14 150.08,1003.28 150.08,1183.58 160.08,1193.58 193.69,1193.58 D2.2
  Bottom Layer w8: v1(255.22,832.68) v1(394.84,832.68)
pads on no net: A1.2 J1. J1.A8 J1.B8 J2.1 J2.4 J2.6 J2.7 J2.19 U1.4 U2.19 U2.20 U2.21 U2.22 U2.23 U2.24 U2.27 U2.28 U4.7

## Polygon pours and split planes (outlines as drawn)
GND on Layer 1 (GND) (split plane): 50.22,1231.87 692.44,1231.87 692.44,1090.98 853.84,1090.98 853.84,709.53 877.84,709.53 877.84,1090.98 992.44,1090.98 992.44,1231.87 1422.11,1231.87 1423.19,1231.98 1426.91,1231.69 1431.48,1230.59 1435.83,1228.79 1439.84,1226.33 1443.42,1223.27 1446.48,1219.69 1448.94,1215.68 1450.74,1211.33 1451.84,1206.75 1452.17,1202.61 1452.12,1202.14 1452.34,1199.85 1452.34,53.32 1452.04,50.25 1452.05,50.2 1452.1,49.69 1451.76,45.45 1450.66,40.87 1448.86,36.52 1446.4,32.51 1443.35,28.93 1439.77,25.87 1435.75,23.42 1431.41,21.61 1426.83,20.52 1422.69,20.19 1422.22,20.24 1420.8,20.1 51.11,20.1 50.32,20.17 50.28,20.17 49.77,20.12 45.52,20.45 40.95,21.55 36.6,23.35 32.59,25.81 29.01,28.87 25.95,32.45 23.49,36.46 21.69,40.81 20.59,45.39 20.23,50.03 20.31,50.03 20.1,52.19 20.1,253.98 20.05,254.45 20.38,258.59 21.48,263.17 23.28,267.51 25.74,271.53 28.79,275.11 32.37,278.16 36.38,280.62 40.73,282.42 45.31,283.52 49.56,283.86 50.06,283.81 50.11,283.8 115.11,283.8 115.25,283.81 122.09,284.15 128.89,285.16 135.56,286.83 142.04,289.15 148.25,292.09 154.15,295.62 159.68,299.72 164.77,304.34 169.39,309.44 173.49,314.96 177.02,320.86 179.97,327.08 182.28,333.55 183.95,340.22 184.96,347.03 185.28,353.49 185.31,353.82 185.31,898.14 185.28,898.46 184.96,904.93 183.95,911.73 182.28,918.41 179.97,924.88 177.02,931.1 173.49,937 169.39,942.52 164.77,947.62 159.68,952.24 154.15,956.33 148.25,959.87 142.04,962.81 135.56,965.13 128.89,966.8 122.09,967.81 117.66,968.03 117.57,968.04 115.75,968.2 113.94,968.37 50.11,968.37 48.34,968.2 45.31,968.44 40.73,969.54 36.38,971.34 32.37,973.8 28.79,976.85 25.74,980.43 23.28,984.45 21.48,988.79 20.38,993.37 20.05,997.51 20.1,997.98 20.1,1199.06 20.39,1202.03 20.39,1202.07 20.34,1202.58 20.67,1206.83 21.77,1211.41 23.57,1215.76 26.03,1219.77 29.09,1223.35 32.66,1226.4 36.68,1228.86 41.02,1230.66 45.6,1231.76 48.78,1232.01
+3.3V on Layer 2 (PWR) (split plane): 50.22,1231.87 692.44,1231.87 692.44,1090.98 853.84,1090.98 853.84,709.68 877.84,709.68 877.84,1090.98 992.44,1090.98 992.44,1231.87 1422.11,1231.87 1423.19,1231.98 1426.91,1231.69 1431.48,1230.59 1435.83,1228.79 1439.84,1226.33 1443.42,1223.27 1446.48,1219.69 1448.94,1215.68 1450.74,1211.33 1451.84,1206.75 1452.17,1202.61 1452.12,1202.14 1452.34,1199.85 1452.34,53.32 1452.04,50.25 1452.05,50.2 1452.1,49.69 1451.76,45.45 1450.66,40.87 1448.86,36.52 1446.4,32.51 1443.35,28.93 1439.77,25.87 1435.75,23.42 1431.41,21.61 1426.83,20.52 1422.69,20.19 1422.22,20.24 1420.8,20.1 51.11,20.1 50.32,20.17 50.28,20.17 49.77,20.12 45.52,20.45 40.95,21.55 36.6,23.35 32.59,25.81 29.01,28.87 25.95,32.45 23.49,36.46 21.69,40.81 20.59,45.39 20.23,50.03 20.31,50.03 20.1,52.19 20.1,253.98 20.05,254.45 20.38,258.59 21.48,263.17 23.28,267.51 25.74,271.53 28.79,275.11 32.37,278.16 36.38,280.62 40.73,282.42 45.31,283.52 49.56,283.86 50.06,283.81 50.11,283.8 115.11,283.8 115.25,283.81 122.09,284.15 128.89,285.16 135.56,286.83 142.04,289.15 148.25,292.09 154.15,295.62 159.68,299.72 164.77,304.34 169.39,309.44 173.49,314.96 177.02,320.86 179.97,327.08 182.28,333.55 183.95,340.22 184.96,347.03 185.28,353.49 185.31,353.82 185.31,898.14 185.28,898.46 184.96,904.93 183.95,911.73 182.28,918.41 179.97,924.88 177.02,931.1 173.49,937 169.39,942.52 164.77,947.62 159.68,952.24 154.15,956.33 148.25,959.87 142.04,962.81 135.56,965.13 128.89,966.8 122.09,967.81 117.66,968.03 117.57,968.04 115.75,968.2 113.94,968.37 50.11,968.37 48.34,968.2 45.31,968.44 40.73,969.54 36.38,971.34 32.37,973.8 28.79,976.85 25.74,980.43 23.28,984.45 21.48,988.79 20.38,993.37 20.05,997.51 20.1,997.98 20.1,1199.06 20.39,1202.03 20.39,1202.07 20.34,1202.58 20.67,1206.83 21.77,1211.41 23.57,1215.76 26.03,1219.77 29.09,1223.35 32.66,1226.4 36.68,1228.86 41.02,1230.66 45.6,1231.76 48.78,1232.01

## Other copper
Top Layer:
  rectangle net GND: 1219.69,448.58 1247.69,508.58
  rectangle net GND: 1219.69,743.58 1248.69,803.58
  pour cut-out: 692.44,1250.98 692.44,1090.98 992.44,1090.98 992.44,1250.98
  text "1" at 1381.69,610.58 h40
Bottom Layer:
  pour cut-out: 692.44,1250.98 692.44,1090.98 992.44,1090.98 992.44,1250.98
  text "4" at 1402.69,610.58 h40
Layer 1 (GND) (plane layer: these items are gaps in the copper):
  pour cut-out: 853.84,1251.82 853.84,709.53 877.84,709.53 877.84,1251.82
  pour cut-out: 692.44,1250.98 692.44,1090.98 992.44,1090.98 992.44,1250.98
  text "2" at 1376.69,610.58 h40
Layer 2 (PWR) (plane layer: these items are gaps in the copper):
  pour cut-out: 853.84,1251.97 853.84,709.68 877.84,709.68 877.84,1251.97
  pour cut-out: 692.44,1250.98 692.44,1090.98 992.44,1090.98 992.44,1250.98
  text "3" at 1376.69,610.58 h40

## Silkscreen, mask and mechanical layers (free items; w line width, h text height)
Top Overlay:
  text "QwiiC" at 1412.69,1068.97 h35 r90
  text "Sensor" at 1286.69,838.97 h30
  text "CHG" at 876.69,458.97 h35
  text "ESP32-C3" at 903.89,107 h40
  text "E-INK" at 1253.89,107 h40
  text "-" at 537,62.01 h40
  text "+" at 712,60.34 h40
  text "1.54\"" at 908.89,32 h40
  text "REV 2.0" at 1176,32 h40
  text "RESET" at 156.69,23.97 h35
  text "IO9" at 396.69,23.97 h35
  text "LiPo" at 582,22 h35
Mechanical 1:
  lines w10: 0,50 0,253.98 cw(c50,253.9) 50.11,303.9 ; 0,1202.03 0,997.98 ccw(c50,998.06) 50.11,948.06 ; 0.22,50 ccw(c50.22,50.08) 50.32,0.08 ; 0.29,1202.03 cw(c50.29,1202.14) 50.22,1252.14 ; 50.11,948.28 113.94,948.28 ; 50.22,1251.97 1422.11,1251.97 ; 50.32,0 1422.22,0 ; 51.28,303.9 115.11,303.9 ccw(c115.22,353.9) 165.22,353.82 165.22,898.14 ccw(c115.22,898.06) 115.11,948.06 ; 1422.11,1252.06 cw(c1422.22,1202.06) 1472.22,1202.14 ; 1422.22,0.14 ccw(c1422.14,50.14) 1472.14,50.25 ; 1472.44,50.25 1472.44,1202.14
